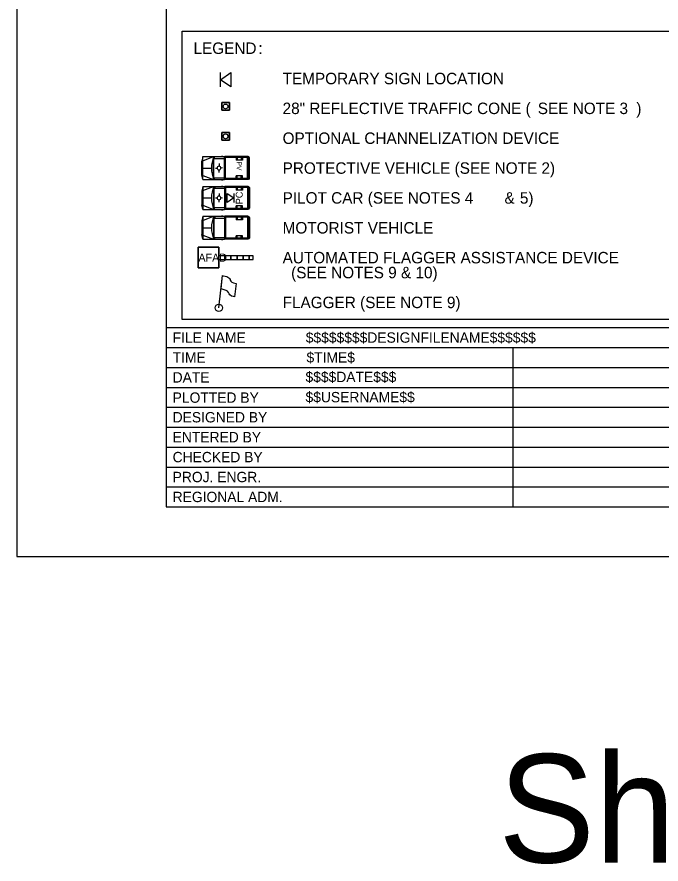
# Model space of a CAD drawing. Extents: x 99999.1 to 100095.7, y 99995 to 100010.7.
# Drawn here: x 99999.06 to 100003.11, y 99997.76 to 100003.08 of the extents above; entities that cross this region are included whole.
import ezdxf

# ---------------------------------------------------------------- set-up
doc = ezdxf.new("R2010")
doc.units = 0
for name, color, linetype in [('SH_GI_PlotLimits', 7, 'Continuous'), ('SH_GI_SheetBorder', 7, 'Continuous'), ('SH_GI_SheetLocationText', 7, 'Continuous'), ('SH_GI_SheetTextInCells', 7, 'Continuous'), ('SH_GI_TitleBlockText', 7, 'Continuous'), ('TR_WZ_AFAD', 7, 'Continuous'), ('TR_WZ_FlaggingStation', 7, 'Continuous'), ('TR_WZ_MotoristVehicle', 7, 'Continuous'), ('TR_WZ_PortableSignMountBlk-Org', 7, 'Continuous'), ('TR_WZ_PortableSignMountBlk-Wht', 7, 'Continuous'), ('TR_WZ_ProtectiveVehicle', 7, 'Continuous'), ('TR_WZ_TrafficCone', 7, 'Continuous'), ('TR_WZ_WorkZoneTextCurrent', 7, 'Continuous')]:
    doc.layers.add(name, color=color, linetype=linetype)

msp = doc.modelspace()

# ---------------------------------------------------------------- linework, layer by layer
at = {"layer": 'SH_GI_PlotLimits'}
msp.add_lwpolyline([(99999.0625, 99999.6875), (100016.0625, 99999.6875), (100016.0625, 100010.6875), (99999.0625, 100010.6875)], close=True, dxfattribs=at)
at = {"layer": 'SH_GI_SheetBorder'}
for p, q in [((100000, 100010.375), (100000, 100000)), ((100000, 100001.1259), (100015.75, 100001.1259)), ((100000, 100001.0008), (100007.4566, 100001.0008)), ((100002.179, 100001.0008), (100002.179, 100000)), ((100000, 100000.8757), (100002.1821, 100000.8757)), ((100002.1821, 100000.8757), (100005.4466, 100000.8757)), ((100000, 100000.7506), (100002.1821, 100000.7506)), ((100002.1821, 100000.7506), (100005.4466, 100000.7506)), ((100000, 100000.6255), (100005.4466, 100000.6255)), ((100000, 100000.5004), (100005.4466, 100000.5004)), ((100000, 100000.3753), (100005.4466, 100000.3753)), ((100000, 100000.2502), (100005.4466, 100000.2502)), ((100000, 100000.1251), (100005.4466, 100000.1251)), ((100000, 100000), (100015.75, 100000))]:
    msp.add_line(p, q, dxfattribs=at)
at = {"layer": 'TR_WZ_AFAD'}
for p, q in [((100000.2009, 100001.5003), (100000.2009, 100001.6299)), ((100000.2009, 100001.6299), (100000.3305, 100001.6299)), ((100000.3305, 100001.6299), (100000.2009, 100001.6299)), ((100000.2009, 100001.6299), (100000.2009, 100001.5003)), ((100000.3305, 100001.6299), (100000.3305, 100001.5003)), ((100000.3305, 100001.5699), (100000.3305, 100001.6299)), ((100000.3689, 100001.5759), (100000.3305, 100001.5759)), ((100000.3305, 100001.5759), (100000.3305, 100001.5699)), ((100000.3305, 100001.5699), (100000.3305, 100001.5651)), ((100000.4073, 100001.5759), (100000.3689, 100001.5759)), ((100000.3689, 100001.5543), (100000.4073, 100001.5543)), ((100000.4457, 100001.5759), (100000.4073, 100001.5759)), ((100000.4073, 100001.5651), (100000.4073, 100001.5759)), ((100000.4073, 100001.5543), (100000.4073, 100001.5651)), ((100000.4073, 100001.5543), (100000.4457, 100001.5543)), ((100000.4841, 100001.5759), (100000.4457, 100001.5759)), ((100000.4457, 100001.5759), (100000.4457, 100001.5651)), ((100000.4457, 100001.5651), (100000.4457, 100001.5543)), ((100000.4457, 100001.5543), (100000.4841, 100001.5543)), ((100000.5225, 100001.5759), (100000.4841, 100001.5759)), ((100000.4841, 100001.5651), (100000.4841, 100001.5759)), ((100000.4841, 100001.5543), (100000.4841, 100001.5651)), ((100000.4841, 100001.5543), (100000.5225, 100001.5543)), ((100000.5225, 100001.5759), (100000.5225, 100001.5651)), ((100000.5225, 100001.5651), (100000.5225, 100001.5543)), ((100000.5225, 100001.5543), (100000.5465, 100001.5543)), ((100000.3305, 100001.5003), (100000.2009, 100001.5003)), ((100000.2009, 100001.5003), (100000.3305, 100001.5003))]:
    msp.add_line(p, q, dxfattribs=at)
for points in [[(100000.3305, 100001.5543), (100000.5465, 100001.5543), (100000.5465, 100001.5759), (100000.3305, 100001.5759)], [(100000.3305, 100001.5003), (100000.3305, 100001.5603), (100000.3305, 100001.5699)], [(100000.3305, 100001.5651), (100000.3305, 100001.5603), (100000.3305, 100001.5543), (100000.3689, 100001.5543)], [(100000.3689, 100001.5543), (100000.3689, 100001.5651), (100000.3689, 100001.5759)], [(100000.3689, 100001.5759), (100000.3689, 100001.5651), (100000.3689, 100001.5543)], [(100000.4073, 100001.5759), (100000.4073, 100001.5651), (100000.4073, 100001.5543)], [(100000.4457, 100001.5543), (100000.4457, 100001.5651), (100000.4457, 100001.5759)], [(100000.4841, 100001.5759), (100000.4841, 100001.5651), (100000.4841, 100001.5543)], [(100000.5225, 100001.5543), (100000.5225, 100001.5651), (100000.5225, 100001.5759)], [(100000.5465, 100001.5543), (100000.5465, 100001.5759), (100000.5225, 100001.5759)]]:
    msp.add_lwpolyline(points, dxfattribs=at)
at = {"layer": 'TR_WZ_FlaggingStation'}
for p, q in [((100000.3314, 100001.2497), (100000.3545, 100001.452)), ((100000.3451, 100001.3699), (100000.3545, 100001.4522)), ((100000.3451, 100001.3699), (100000.3451, 100001.3699)), ((100000.4394, 100001.4034), (100000.4299, 100001.319))]:
    msp.add_line(p, q, dxfattribs=at)
for points in [[(100000.3545, 100001.4522), (100000.3586, 100001.4513), (100000.3715, 100001.4488), (100000.3814, 100001.4458), (100000.3884, 100001.4414), (100000.3945, 100001.438), (100000.3986, 100001.4331), (100000.4017, 100001.4275), (100000.4021, 100001.423), (100000.4059, 100001.4164), (100000.4137, 100001.411), (100000.4226, 100001.4073), (100000.4394, 100001.4034)], [(100000.4299, 100001.319), (100000.424, 100001.32), (100000.4112, 100001.3234), (100000.4, 100001.3309), (100000.3953, 100001.3385), (100000.3925, 100001.3459), (100000.3859, 100001.3538), (100000.378, 100001.3583), (100000.3655, 100001.3634), (100000.3451, 100001.3699)]]:
    msp.add_lwpolyline(points, dxfattribs=at)
msp.add_circle((100000.3314, 100001.2497), 0.0234, dxfattribs=at)
at = {"layer": 'TR_WZ_MotoristVehicle'}
for p, q in [((100000.2305, 100002.012), (100000.2239, 100001.9829)), ((100000.2305, 100002.012), (100000.2305, 100001.868)), ((100000.2305, 100002.012), (100000.3665, 100002.012)), ((100000.2305, 100001.9856), (100000.2985, 100002.012)), ((100000.2985, 100002.012), (100000.2985, 100001.868)), ((100000.2998, 100002.012), (100000.2998, 100001.868)), ((100000.2998, 100002.012), (100000.3084, 100002.0008)), ((100000.348, 100002.014), (100000.3562, 100002.014)), ((100000.3665, 100002.012), (100000.3665, 100001.868)), ((100000.5166, 100002.012), (100000.3685, 100002.012)), ((100000.3685, 100002.012), (100000.3685, 100001.868)), ((100000.5166, 100002.012), (100000.5166, 100001.868)), ((100000.5204, 100002.0096), (100000.5171, 100002.0096)), ((100000.5171, 100002.0096), (100000.5171, 100001.8704)), ((100000.2239, 100001.9829), (100000.2239, 100001.8971)), ((100000.2998, 100002.0008), (100000.3665, 100002.0008)), ((100000.3324, 100001.9685), (100000.3324, 100001.9569)), ((100000.5124, 100002.0062), (100000.3727, 100002.0062)), ((100000.3727, 100002.0062), (100000.3727, 100001.8737)), ((100000.4395, 100002.0062), (100000.4395, 100001.9897)), ((100000.4791, 100001.9897), (100000.4395, 100001.9897)), ((100000.4467, 100002.0062), (100000.4467, 100001.9897)), ((100000.4711, 100002.0062), (100000.4711, 100001.9897)), ((100000.4791, 100002.0062), (100000.4791, 100001.9897)), ((100000.5124, 100002.0062), (100000.5124, 100001.8737)), ((100000.5236, 100002.0052), (100000.5236, 100001.8747)), ((100000.2305, 100001.94), (100000.2852, 100001.94)), ((100000.3107, 100001.9401), (100000.3198, 100001.94)), ((100000.3329, 100001.9123), (100000.3327, 100001.9231)), ((100000.3426, 100001.9397), (100000.3426, 100001.9397)), ((100000.3546, 100001.9394), (100000.3439, 100001.9397)), ((100000.5236, 100001.9501), (100000.5171, 100001.9474)), ((100000.5236, 100001.9298), (100000.5171, 100001.9325)), ((100000.5218, 100001.94), (100000.5189, 100001.94)), ((100000.5204, 100001.942), (100000.5204, 100001.938)), ((100000.2305, 100001.868), (100000.2239, 100001.8971)), ((100000.2305, 100001.8944), (100000.2985, 100001.868)), ((100000.2305, 100001.868), (100000.3665, 100001.868)), ((100000.2998, 100001.8791), (100000.3665, 100001.8791)), ((100000.3069, 100001.8791), (100000.2998, 100001.868)), ((100000.348, 100001.866), (100000.3562, 100001.866)), ((100000.5166, 100001.868), (100000.3685, 100001.868)), ((100000.5124, 100001.8737), (100000.3727, 100001.8737)), ((100000.4395, 100001.8737), (100000.4395, 100001.8903)), ((100000.4791, 100001.8903), (100000.4395, 100001.8903)), ((100000.4467, 100001.8737), (100000.4467, 100001.8903)), ((100000.4711, 100001.8737), (100000.4711, 100001.8903)), ((100000.4791, 100001.8737), (100000.4791, 100001.8903)), ((100000.5204, 100001.8704), (100000.5171, 100001.8704)), ((100000.2305, 100001.8245), (100000.2239, 100001.7955)), ((100000.2239, 100001.7955), (100000.2239, 100001.7096)), ((100000.2305, 100001.8245), (100000.2305, 100001.6805)), ((100000.2305, 100001.8245), (100000.3665, 100001.8245)), ((100000.2305, 100001.7982), (100000.2985, 100001.8245)), ((100000.2985, 100001.8245), (100000.2985, 100001.6805)), ((100000.2998, 100001.8245), (100000.2998, 100001.6805)), ((100000.2998, 100001.8245), (100000.3084, 100001.8134)), ((100000.2998, 100001.8134), (100000.3665, 100001.8134)), ((100000.348, 100001.8266), (100000.3562, 100001.8266)), ((100000.3665, 100001.8245), (100000.3665, 100001.6805)), ((100000.5166, 100001.8245), (100000.3685, 100001.8245)), ((100000.3685, 100001.8245), (100000.3685, 100001.6805)), ((100000.5124, 100001.8188), (100000.3727, 100001.8188)), ((100000.3727, 100001.8188), (100000.3727, 100001.6863)), ((100000.4395, 100001.8188), (100000.4395, 100001.8022)), ((100000.4791, 100001.8022), (100000.4395, 100001.8022)), ((100000.4467, 100001.8188), (100000.4467, 100001.8022)), ((100000.4711, 100001.8188), (100000.4711, 100001.8022)), ((100000.4791, 100001.8188), (100000.4791, 100001.8022)), ((100000.5124, 100001.8188), (100000.5124, 100001.6863)), ((100000.5166, 100001.8245), (100000.5166, 100001.6805)), ((100000.5204, 100001.8222), (100000.5171, 100001.8222)), ((100000.5171, 100001.8222), (100000.5171, 100001.6829)), ((100000.5236, 100001.8178), (100000.5236, 100001.6873)), ((100000.2305, 100001.7525), (100000.2852, 100001.7525)), ((100000.5236, 100001.7627), (100000.5171, 100001.76)), ((100000.5236, 100001.7424), (100000.5171, 100001.7451)), ((100000.5218, 100001.7525), (100000.5189, 100001.7525)), ((100000.5204, 100001.7546), (100000.5204, 100001.7505)), ((100000.2305, 100001.6805), (100000.2239, 100001.7096)), ((100000.2305, 100001.7069), (100000.2985, 100001.6805)), ((100000.2998, 100001.6917), (100000.3665, 100001.6917)), ((100000.3069, 100001.6917), (100000.2998, 100001.6805)), ((100000.4395, 100001.6863), (100000.4395, 100001.7028)), ((100000.4791, 100001.7028), (100000.4395, 100001.7028)), ((100000.4467, 100001.6863), (100000.4467, 100001.7028)), ((100000.4711, 100001.6863), (100000.4711, 100001.7028)), ((100000.4791, 100001.6863), (100000.4791, 100001.7028)), ((100000.2305, 100001.6805), (100000.3665, 100001.6805)), ((100000.348, 100001.6785), (100000.3562, 100001.6785)), ((100000.5166, 100001.6805), (100000.3685, 100001.6805)), ((100000.5124, 100001.6863), (100000.3727, 100001.6863)), ((100000.5204, 100001.6829), (100000.5171, 100001.6829))]:
    msp.add_line(p, q, dxfattribs=at)
for centre, major_axis, start_param, end_param in [((100000.3957, 100001.94), (0, -0.1511), 4.215667, 5.208926), ((100000.5204, 100002.0052), (0, 0.00439), 4.712389, 6.283185), ((100000.5204, 100001.8747), (0, -0.00439), 0, 1.570796), ((100000.3957, 100001.7525), (0, -0.1511), 4.215667, 5.208926), ((100000.5204, 100001.8178), (0, 0.00439), 4.712389, 6.283185), ((100000.5204, 100001.6873), (0, -0.00439), 0, 1.570796)]:
    msp.add_ellipse(centre, major_axis=major_axis, ratio=0.73155, start_param=start_param, end_param=end_param, dxfattribs=at)
for centre, major_axis in [((100000.3324, 100001.94), (0, 0.0139)), ((100000.5204, 100001.94), (0, 0.00203)), ((100000.5204, 100001.7525), (0, 0.00203))]:
    msp.add_ellipse(centre, major_axis=major_axis, ratio=0.73155, dxfattribs=at)
at = {"layer": 'TR_WZ_PortableSignMountBlk-Org'}
msp.add_line((100000.3414, 100002.6372), (100000.3414, 100002.7272), dxfattribs=at)
msp.add_lwpolyline([(100000.3414, 100002.6821), (100000.406, 100002.7272), (100000.406, 100002.6372)], close=True, dxfattribs=at)
at = {"layer": 'TR_WZ_PortableSignMountBlk-Wht'}
msp.add_line((100000.4259, 100001.9687), (100000.4259, 100001.9111), dxfattribs=at)
msp.add_lwpolyline([(100000.4259, 100001.94), (100000.3845, 100001.9111), (100000.3845, 100001.9687)], close=True, dxfattribs=at)
at = {"layer": 'TR_WZ_ProtectiveVehicle'}
for p, q in [((100000.2305, 100002.1994), (100000.2239, 100002.1704)), ((100000.2239, 100002.0845), (100000.2239, 100002.1704)), ((100000.2305, 100002.0554), (100000.2305, 100002.1994)), ((100000.2305, 100002.1994), (100000.3665, 100002.1994)), ((100000.2305, 100002.1731), (100000.2985, 100002.1994)), ((100000.2985, 100002.0554), (100000.2985, 100002.1994)), ((100000.2998, 100002.0554), (100000.2998, 100002.1994)), ((100000.3069, 100002.1883), (100000.2998, 100002.1994)), ((100000.2998, 100002.1883), (100000.3665, 100002.1883)), ((100000.348, 100002.2015), (100000.3562, 100002.2015)), ((100000.3665, 100002.0554), (100000.3665, 100002.1994)), ((100000.5166, 100002.1994), (100000.3685, 100002.1994)), ((100000.3685, 100002.0554), (100000.3685, 100002.1994)), ((100000.5124, 100002.1937), (100000.3727, 100002.1937)), ((100000.3727, 100002.0612), (100000.3727, 100002.1937)), ((100000.4395, 100002.1937), (100000.4395, 100002.1771)), ((100000.4791, 100002.1771), (100000.4395, 100002.1771)), ((100000.4467, 100002.1937), (100000.4467, 100002.1771)), ((100000.4711, 100002.1937), (100000.4711, 100002.1771)), ((100000.4791, 100002.1937), (100000.4791, 100002.1771)), ((100000.5124, 100002.0612), (100000.5124, 100002.1937)), ((100000.5166, 100002.0554), (100000.5166, 100002.1994)), ((100000.5204, 100002.1971), (100000.5171, 100002.1971)), ((100000.5171, 100002.0578), (100000.5171, 100002.1971)), ((100000.5236, 100002.0622), (100000.5236, 100002.1927)), ((100000.2305, 100002.1274), (100000.2852, 100002.1274)), ((100000.3107, 100002.1273), (100000.3198, 100002.1274)), ((100000.3329, 100002.1551), (100000.3327, 100002.1443)), ((100000.3426, 100002.1277), (100000.3426, 100002.1277)), ((100000.3546, 100002.128), (100000.3439, 100002.1277)), ((100000.5236, 100002.1376), (100000.5171, 100002.1349)), ((100000.5236, 100002.1173), (100000.5171, 100002.12)), ((100000.5218, 100002.1274), (100000.5189, 100002.1274)), ((100000.5204, 100002.1254), (100000.5204, 100002.1295)), ((100000.2305, 100002.0554), (100000.2239, 100002.0845)), ((100000.2305, 100002.0818), (100000.2985, 100002.0554)), ((100000.2998, 100002.0554), (100000.3084, 100002.0666)), ((100000.2998, 100002.0666), (100000.3665, 100002.0666)), ((100000.3324, 100002.0989), (100000.3324, 100002.1105)), ((100000.5124, 100002.0612), (100000.3727, 100002.0612)), ((100000.4791, 100002.0777), (100000.4395, 100002.0777)), ((100000.4395, 100002.0612), (100000.4395, 100002.0777)), ((100000.4467, 100002.0612), (100000.4467, 100002.0777)), ((100000.4711, 100002.0612), (100000.4711, 100002.0777)), ((100000.4791, 100002.0612), (100000.4791, 100002.0777)), ((100000.2305, 100002.0554), (100000.3665, 100002.0554)), ((100000.348, 100002.0534), (100000.3562, 100002.0534)), ((100000.5166, 100002.0554), (100000.3685, 100002.0554)), ((100000.5204, 100002.0578), (100000.5171, 100002.0578))]:
    msp.add_line(p, q, dxfattribs=at)
for centre, major_axis, start_param, end_param in [((100000.3957, 100002.1275), (0, -0.1511), 4.215852, 5.209111), ((100000.5204, 100002.1927), (0, 0.00439), 4.712389, 6.283185), ((100000.5204, 100002.0622), (0, -0.00439), 6.283185, 7.853982)]:
    msp.add_ellipse(centre, major_axis=major_axis, ratio=0.73155, start_param=start_param, end_param=end_param, dxfattribs=at)
for centre, major_axis in [((100000.3324, 100002.1274), (0, 0.0139)), ((100000.5204, 100002.1274), (0, 0.00203))]:
    msp.add_ellipse(centre, major_axis=major_axis, ratio=0.73155, dxfattribs=at)
at = {"layer": 'TR_WZ_TrafficCone'}
for points in [[(100000.3497, 100002.5383), (100000.3977, 100002.5383), (100000.3977, 100002.4903), (100000.3497, 100002.4903), (100000.3497, 100002.5383)], [(100000.3497, 100002.4903), (100000.3977, 100002.4903), (100000.3977, 100002.5383), (100000.3497, 100002.5383), (100000.3497, 100002.4903)], [(100000.3497, 100002.3508), (100000.3977, 100002.3508), (100000.3977, 100002.3028), (100000.3497, 100002.3028), (100000.3497, 100002.3508)], [(100000.3497, 100002.3028), (100000.3977, 100002.3028), (100000.3977, 100002.3508), (100000.3497, 100002.3508), (100000.3497, 100002.3028)]]:
    msp.add_lwpolyline(points, dxfattribs=at)
for centre in [(100000.3737, 100002.5143), (100000.3737, 100002.3268)]:
    msp.add_circle(centre, 0.015, dxfattribs=at)
at = {"layer": 'TR_WZ_WorkZoneTextCurrent'}
msp.add_lwpolyline([(100000.1, 100002.9879), (100003.2886, 100002.9879), (100003.2886, 100001.1759), (100000.1, 100001.1759)], close=True, dxfattribs=at)

# ---------------------------------------------------------------- texts
at = {"layer": 'SH_GI_SheetLocationText'}
msp.add_text('Shared Bike-Vehicle Lane', height=0.68, dxfattribs=at).set_placement((100002.0877, 99997.7671))
at = {"layer": 'SH_GI_SheetTextInCells'}
for s, height, p in [('FILE NAME', 0.06505, (100000.041, 100001.0308)), ('TIME', 0.06505, (100000.041, 100000.9057)), ('DATE', 0.06505, (100000.041, 100000.7806)), ('PLOTTED BY', 0.06505, (100000.041, 100000.6538)), ('DESIGNED BY', 0.065052, (100000.041, 100000.5304)), ('ENTERED BY', 0.06505, (100000.041, 100000.4053)), ('CHECKED BY', 0.06505, (100000.041, 100000.2802)), ('PROJ. ENGR.', 0.065052, (100000.041, 100000.1551)), ('REGIONAL ADM.', 0.065052, (100000.041, 100000.03))]:
    msp.add_text(s, height=height, dxfattribs=at).set_placement(p)
at = {"layer": 'SH_GI_TitleBlockText'}
for s, height, p in [('$$$$$$$$DESIGNFILENAME$$$$$$', 0.065052, (100000.8775, 100001.0308)), ('$TIME$', 0.06505, (100000.882, 100000.9059)), ('$$$$DATE$$$', 0.065052, (100000.8759, 100000.7835)), ('$$USERNAME$$', 0.065052, (100000.8759, 100000.6567))]:
    msp.add_text(s, height=height, dxfattribs=at).set_placement(p)
at = {"layer": 'TR_WZ_AFAD'}
msp.add_text('AFAD', height=0.0504, dxfattribs=at).set_placement((100000.203, 100001.5399))
at = {"layer": 'TR_WZ_MotoristVehicle'}
msp.add_text('PC', height=0.0432, rotation=90, dxfattribs=at).set_placement((100000.4809, 100001.8996))
at = {"layer": 'TR_WZ_ProtectiveVehicle'}
msp.add_text('PV', height=0.03006, rotation=270, dxfattribs=at).set_placement((100000.4442, 100002.1682))
at = {"layer": 'TR_WZ_WorkZoneTextCurrent'}
for s, p in [('LEGEND', (100000.172, 100002.8439)), (':', (100000.5795, 100002.8439)), ('TEMPORARY SIGN LOCATION ', (100000.732, 100002.6538)), ('28" REFLECTIVE TRAFFIC CONE (', (100000.732, 100002.4663)), ('SEE NOTE 3', (100002.3354, 100002.4663)), (')', (100002.9549, 100002.4663)), ('OPTIONAL CHANNELIZATION DEVICE', (100000.732, 100002.2789)), ('PROTECTIVE VEHICLE (SEE NOTE 2)', (100000.732, 100002.0914)), ('PILOT CAR (SEE NOTES 4', (100000.732, 100001.904)), ('&', (100002.1264, 100001.904)), ('5)', (100002.2229, 100001.904)), ('MOTORIST VEHICLE', (100000.732, 100001.7165)), ('AUTOMATED FLAGGER ASSISTANCE DEVICE', (100000.732, 100001.5291)), ('  (SEE NOTES 9 & 10)', (100000.732, 100001.4354)), ('FLAGGER (SEE NOTE 9)', (100000.732, 100001.2479))]:
    msp.add_text(s, height=0.072, rotation=360, dxfattribs=at).set_placement(p)

doc.saveas('drawing.dxf')
